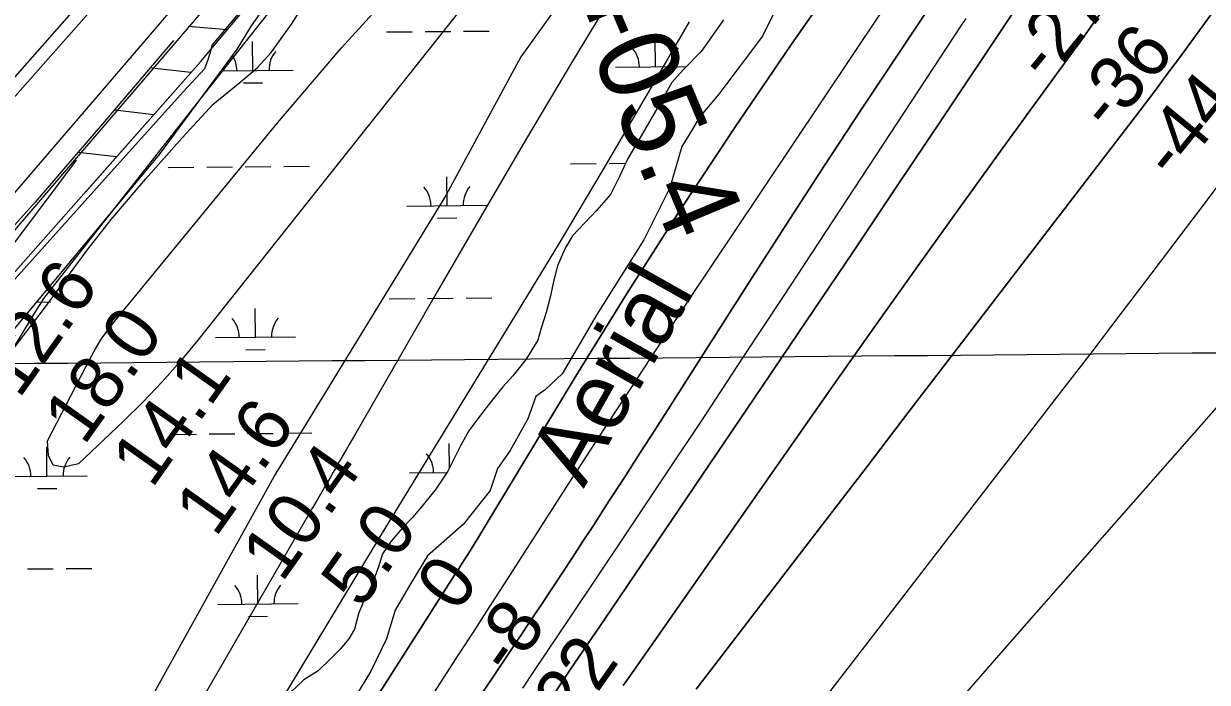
# Model space of a CAD drawing. Extents: x 3598634 to 3636690, y 517270 to 542944.
# Drawn here: x 3604186 to 3605662, y 528352 to 529174 of the extents above; entities that cross this region are included whole.
import ezdxf

# ---------------------------------------------------------------- set-up
doc = ezdxf.new("R2010")
doc.units = 0
for name, color, linetype in [('V-FLOD-BASE', 7, 'Continuous'), ('V-GRID-MAJR', 7, 'Continuous'), ('V-LEVE-TOET', 7, 'Continuous'), ('V-RIVR-EDGE', 7, 'Continuous'), ('V-RIVR-IDEN', 7, 'Continuous'), ('V-RIVR-RANG', 7, 'Continuous'), ('V-ROAD-CNTR', 7, 'Continuous'), ('V-RRAP-FSHR', 7, 'Continuous'), ('V-SITE-VEGE', 7, 'Continuous'), ('V-SURV-IDEN', 7, 'Continuous'), ('V-SURV-LINE', 7, 'Continuous'), ('V-TOPO-DPTH', 7, 'Continuous'), ('V-TOPO-MAJR', 7, 'Continuous'), ('V-TOPO-MINR', 7, 'Continuous'), ('V-TOPO-WATR', 7, 'Continuous'), ('V-WETL-SWMP', 7, 'Continuous')]:
    doc.layers.add(name, color=color, linetype=linetype)

msp = doc.modelspace()

# ---------------------------------------------------------------- linework, layer by layer
at = {"layer": 'V-FLOD-BASE'}
msp.add_lwpolyline([(3604373.2, 529152.8), (3604289.3, 529054.6), (3604200.6, 528951.2), (3604076.2, 528813.1), (3603925.5, 528633), (3603780.1, 528463.8), (3603729.2, 528402.9)], dxfattribs=at)
at = {"layer": 'V-GRID-MAJR'}
msp.add_spline([(3602797.9, 528737.7), (3608075.8, 528784.9), (3613353.8, 528832.9), (3618631.7, 528881.6), (3623909.7, 528931.1), (3629187.6, 528981.4), (3634465.5, 529032.5), (3634465.6, 529032.5)], degree=3, dxfattribs=at)
at = {"layer": 'V-LEVE-TOET'}
for points in [[(3605056.3, 530112.1), (3604790.8, 529796.4), (3604573.6, 529540.7), (3604353.6, 529284.8), (3604111.5, 529011.5), (3603916.4, 528772.2)], [(3605050.3, 529879.7), (3604869.8, 529677.4), (3604720.6, 529504.1), (3604655.2, 529427.9), (3604632.9, 529402.5), (3604606.9, 529368.5), (3604570.5, 529321.8), (3604548.7, 529296.4), (3604525.3, 529269.3), (3604483.9, 529222.5), (3604421.3, 529147.5), (3604419.3, 529139.5), (3604415.7, 529128.7), (3604411.5, 529117.3), (3604385.3, 529089), (3604295.3, 528989), (3604145.9, 528823), (3604017, 528671.5)]]:
    msp.add_lwpolyline(points, dxfattribs=at)
at = {"layer": 'V-RIVR-EDGE'}
msp.add_lwpolyline([(3605143.9, 529232), (3605107.6, 529158), (3605052.8, 529085.8), (3605028.9, 529057.1), (3605019, 529039.9), (3605006.7, 529020.4), (3604991.9, 528968.9), (3604959.3, 528904.1), (3604900.8, 528811.1), (3604857.7, 528737), (3604836.9, 528717.5), (3604824.6, 528708.9), (3604814.7, 528680.8), (3604792.6, 528641.6), (3604777.2, 528619), (3604767.9, 528591.4), (3604734.1, 528549.2), (3604689.9, 528510.1), (3604668.4, 528475.3), (3604649.3, 528442.2), (3604638.8, 528406.7), (3604619.1, 528366.3), (3604599.4, 528333.9)], dxfattribs=at)
at = {"layer": 'V-ROAD-CNTR'}
msp.add_lwpolyline([(3605050.3, 530130.1), (3604771, 529801.9), (3604661.3, 529672.6), (3604570.1, 529565.2), (3604473.3, 529450.7), (3604385.1, 529346.4), (3604329.2, 529282.9), (3604137.8, 529065.5), (3604133.8, 529061), (3603910.1, 528798.8), (3603670.9, 528524.4), (3603437, 528243.4)], dxfattribs=at)
at = {"layer": 'V-RRAP-FSHR'}
for p, q in [((3604440, 529166.1), (3604391.4, 529170.3)), ((3604394.7, 529112.7), (3604346.2, 529118.2)), ((3604348.4, 529060.2), (3604299.9, 529065.7)), ((3604302.1, 529007.7), (3604253.6, 529013.2))]:
    msp.add_line(p, q, dxfattribs=at)
for points in [[(3603091.9, 527329.5), (3603199.9, 527468.8), (3603247.5, 527548.8), (3603278.3, 527622.7), (3603286.7, 527683.9), (3603300.5, 527779.2), (3603315.4, 527834.6), (3603329.5, 527870), (3603360.8, 527909.2), (3603408.7, 527958.4), (3603635.1, 528229.7), (3603874.5, 528509.5), (3604166.6, 528854.3), (3604406.6, 529126.1), (3604875.1, 529685.7), (3605090, 529929.6)], [(3604263.2, 528963.7), (3604406.6, 529126.1), (3604800.2, 529596.2)]]:
    msp.add_lwpolyline(points, dxfattribs=at)
at = {"layer": 'V-SITE-VEGE'}
for p, q in [((3604886.8, 529244.8), (3604806.2, 529132.3)), ((3604520, 529173), (3604544, 529210.9)), ((3604494.6, 529137.6), (3604520, 529173)), ((3604477.2, 529118.5), (3604494.6, 529137.6)), ((3604806.2, 529132.3), (3604712.4, 528959.5)), ((3604455.6, 529100.5), (3604477.2, 529118.5)), ((3604422.3, 529073.2), (3604455.6, 529100.5)), ((3604383.9, 529031.3), (3604422.3, 529073.2)), ((3604338.1, 528979.7), (3604383.9, 529031.3)), ((3604295.3, 528929.3), (3604338.1, 528979.7)), ((3604712.4, 528959.5), (3604500.4, 528612.5)), ((3604265.3, 528891.3), (3604295.3, 528929.3)), ((3604211.1, 528817.3), (3604265.3, 528891.3)), ((3604171.3, 528765.8), (3604211.1, 528817.3)), ((3604500.4, 528612.5), (3604322.2, 528291.7))]:
    msp.add_line(p, q, dxfattribs=at)
at = {"layer": 'V-SURV-LINE'}
for points in [[(3603326, 527973.1), (3604734.6, 529615.8)], [(3604757.4, 529596.2), (3603348.8, 527953.6)]]:
    msp.add_lwpolyline(points, dxfattribs=at)
at = {"layer": 'V-TOPO-DPTH'}
for points in [[(3604845.8, 528335.7), (3604867.3, 528367.4), (3604888.8, 528399.2), (3604910.3, 528430.9), (3605107.1, 528721.4), (3605163.3, 528804.6), (3605219.5, 528887.9), (3605275.5, 528971.4), (3605331.4, 529054.9), (3605410.1, 529172.8), (3605426.6, 529197.4), (3605443, 529221.9), (3605459.6, 529246.4), (3605476.1, 529270.9), (3605537, 529360.8), (3605584.1, 529430.1), (3605631.4, 529499.3), (3605678.9, 529568.4), (3605726.6, 529637.3), (3606120.2, 530204.3)], [(3606120.2, 530204.3), (3605726.6, 529637.3), (3605678.9, 529568.4), (3605631.4, 529499.3), (3605584.1, 529430.1), (3605537, 529360.8), (3605476.1, 529270.9), (3605459.6, 529246.4), (3605443, 529221.9), (3605426.6, 529197.4), (3605410.1, 529172.8), (3605331.4, 529054.9), (3605275.5, 528971.4), (3605219.5, 528887.9), (3605163.3, 528804.6), (3605107.1, 528721.4), (3604910.3, 528430.9), (3604888.8, 528399.2), (3604867.3, 528367.4), (3604845.8, 528335.7)], [(3605024.7, 528344), (3605083.8, 528420.9), (3605135.1, 528487.9), (3605186.4, 528554.8), (3605237.8, 528621.7), (3605289.1, 528688.7), (3605573.7, 529059.5), (3605586.9, 529076.9), (3605600.1, 529094.3), (3605613, 529111.8), (3605626, 529129.4), (3605745.9, 529294.1), (3605818.7, 529394.1), (3605891.6, 529494), (3605964.5, 529594), (3606037.5, 529693.9), (3606273.1, 530016.3)], [(3606273.1, 530016.3), (3606037.5, 529693.9), (3605964.5, 529594), (3605891.6, 529494), (3605818.7, 529394.1), (3605745.9, 529294.1), (3605626, 529129.4), (3605613, 529111.8), (3605600.1, 529094.3), (3605586.9, 529076.9), (3605573.7, 529059.5), (3605289.1, 528688.7), (3605237.8, 528621.7), (3605186.4, 528554.8), (3605135.1, 528487.9), (3605083.8, 528420.9), (3605024.7, 528344)], [(3604933.7, 528348.5), (3604946.8, 528367.3), (3605196.3, 528723.6), (3605248.4, 528797.4), (3605300.7, 528871.1), (3605353.4, 528944.5), (3605406.3, 529017.7), (3605494, 529138.2), (3605503.3, 529151), (3605512.5, 529163.9), (3605521.7, 529176.8), (3605530.9, 529189.7), (3605600.5, 529288.5), (3605644.1, 529351.1), (3605687.2, 529413.9), (3605729.7, 529477.3), (3605771.8, 529540.9), (3605859.2, 529674.6), (3605898.9, 529735), (3605938.7, 529795.4), (3605978.6, 529855.6), (3606018.7, 529915.8)], [(3606018.7, 529915.8), (3605978.6, 529855.6), (3605938.7, 529795.4), (3605898.9, 529735), (3605859.2, 529674.6), (3605771.8, 529540.9), (3605729.7, 529477.3), (3605687.2, 529413.9), (3605644.1, 529351.1), (3605600.5, 529288.5), (3605530.9, 529189.7), (3605521.7, 529176.8), (3605512.5, 529163.9), (3605503.3, 529151), (3605494, 529138.2), (3605406.3, 529017.7), (3605353.4, 528944.5), (3605300.7, 528871.1), (3605248.4, 528797.4), (3605196.3, 528723.6), (3604946.8, 528367.3), (3604933.7, 528348.5)], [(3605249.9, 529300.6), (3605142.8, 529146.8), (3605072.9, 529044.3), (3605004.3, 528940.9), (3604937.8, 528836.2), (3604872.5, 528730.7), (3604751.9, 528531.2), (3604748, 528524.8), (3604744, 528518.3), (3604740, 528511.9), (3604735.9, 528505.6), (3604733.7, 528502.1), (3604730.8, 528497.5), (3604727.8, 528492.8), (3604724.8, 528488.2), (3604721.8, 528483.6), (3604718.8, 528479), (3604715.9, 528474.4), (3604712.9, 528469.7), (3604709.9, 528465.1), (3604239.5, 527726.4)], [(3604239.5, 527726.4), (3604709.9, 528465.1), (3604712.9, 528469.7), (3604715.9, 528474.4), (3604718.8, 528479), (3604721.8, 528483.6), (3604724.8, 528488.2), (3604727.8, 528492.8), (3604730.8, 528497.5), (3604733.7, 528502.1), (3604735.9, 528505.6), (3604740, 528511.9), (3604744, 528518.3), (3604748, 528524.8), (3604751.9, 528531.2), (3604872.5, 528730.7), (3604937.8, 528836.2), (3605004.3, 528940.9), (3605072.9, 529044.3), (3605142.8, 529146.8), (3605249.9, 529300.6)], [(3605345.1, 529238.9), (3605278.1, 529138.3), (3605230.8, 529067), (3605183.8, 528995.4), (3605137.2, 528923.6), (3605090.9, 528851.5), (3604973.8, 528668.1), (3604954.6, 528638.1), (3604935.3, 528608), (3604915.9, 528578.1), (3604896.5, 528548.1), (3604883.1, 528527.4), (3604870.4, 528507.9), (3604857.6, 528488.4), (3604844.7, 528468.9), (3604831.8, 528449.5), (3604813.7, 528422.3), (3604809.8, 528416.5), (3604806, 528410.7), (3604802.1, 528404.9), (3604798.3, 528399.2), (3604199.6, 527503.6)], [(3604199.6, 527503.6), (3604798.3, 528399.2), (3604802.1, 528404.9), (3604806, 528410.7), (3604809.8, 528416.5), (3604813.7, 528422.3), (3604831.8, 528449.5), (3604844.7, 528468.9), (3604857.6, 528488.4), (3604870.4, 528507.9), (3604883.1, 528527.4), (3604896.5, 528548.1), (3604915.9, 528578.1), (3604935.3, 528608), (3604954.6, 528638.1), (3604973.8, 528668.1), (3605090.9, 528851.5), (3605137.2, 528923.6), (3605183.8, 528995.4), (3605230.8, 529067), (3605278.1, 529138.3), (3605345.1, 529238.9)], [(3604926.2, 529219.3), (3604869.4, 529124.9), (3604813, 529030.3), (3604757.4, 528935.3), (3604702.1, 528840), (3604600.2, 528663), (3604596.2, 528656.1), (3604592.2, 528649.1), (3604588.2, 528642.2), (3604584.2, 528635.2), (3604580.2, 528628.3), (3604576.2, 528621.3), (3604572.2, 528614.4), (3604568.2, 528607.5), (3604566.3, 528604.2), (3604561.3, 528595.6), (3604556.3, 528587), (3604551.4, 528578.4), (3604546.4, 528569.8), (3604348.9, 528227.9)]]:
    msp.add_lwpolyline(points, dxfattribs=at)
at = {"layer": 'V-TOPO-MAJR'}
msp.add_lwpolyline([(3606410.5, 529960.7), (3606338.7, 529867.2), (3606297.8, 529813.6), (3606257.1, 529759.9), (3606216.7, 529705.9), (3606176.6, 529651.7), (3605749.4, 529071.5), (3605726.4, 529040.4), (3605703.4, 529009.4), (3605680.2, 528978.4), (3605657, 528947.5), (3605629.1, 528910.6), (3605591.8, 528861.3), (3605554.4, 528812.1), (3605516.8, 528763), (3605479.1, 528714), (3605128, 528259)], dxfattribs=at)
at = {"layer": 'V-TOPO-MINR'}
for points in [[(3605455.6, 530362.7), (3604918.8, 529698.1), (3604908.1, 529684.9), (3604897.3, 529671.8), (3604886.3, 529658.7), (3604875.4, 529645.7), (3604732.8, 529478.9), (3604651, 529382), (3604570.1, 529284.5), (3604490.4, 529186), (3604411.5, 529086.8), (3604219.9, 528842.7), (3604215.4, 528836.8), (3604211.1, 528830.8), (3604207, 528824.7), (3604203, 528818.4), (3604074.2, 528606.6), (3604034.4, 528543.7)], [(3606051.8, 530242.9), (3605366.7, 529350.5), (3605361.7, 529343.9), (3605356.6, 529337.2), (3605351.7, 529330.6), (3605346.7, 529323.9), (3605341.9, 529317.2), (3605337.1, 529310.4), (3605332.3, 529303.6), (3605327.7, 529296.7), (3605071.1, 528912.9), (3605019.1, 528834.7), (3604967.3, 528756.3), (3604916, 528677.7), (3604864.9, 528598.9), (3604796.4, 528492.6), (3604779.8, 528466.8), (3604763.1, 528441), (3604746.5, 528415.1), (3604729.8, 528389.3), (3604653.7, 528271.2)], [(3606120.2, 530204.3), (3605726.6, 529637.3), (3605678.9, 529568.4), (3605631.4, 529499.3), (3605584.1, 529430.1), (3605537, 529360.8), (3605476.1, 529270.9), (3605459.6, 529246.4), (3605443, 529221.9), (3605426.6, 529197.4), (3605410.1, 529172.8), (3605331.4, 529054.9), (3605275.5, 528971.4), (3605219.5, 528887.9), (3605163.3, 528804.6), (3605107.1, 528721.4), (3604910.3, 528430.9), (3604888.8, 528399.2), (3604867.3, 528367.4), (3604845.8, 528335.7)], [(3606273.1, 530016.3), (3606037.5, 529693.9), (3605964.5, 529594), (3605891.6, 529494), (3605818.7, 529394.1), (3605745.9, 529294.1), (3605626, 529129.4), (3605613, 529111.8), (3605600.1, 529094.3), (3605586.9, 529076.9), (3605573.7, 529059.5), (3605289.1, 528688.7), (3605237.8, 528621.7), (3605186.4, 528554.8), (3605135.1, 528487.9), (3605083.8, 528420.9), (3605024.7, 528344)], [(3606018.7, 529915.8), (3605978.6, 529855.6), (3605938.7, 529795.4), (3605898.9, 529735), (3605859.2, 529674.6), (3605771.8, 529540.9), (3605729.7, 529477.3), (3605687.2, 529413.9), (3605644.1, 529351.1), (3605600.5, 529288.5), (3605530.9, 529189.7), (3605521.7, 529176.8), (3605512.5, 529163.9), (3605503.3, 529151), (3605494, 529138.2), (3605406.3, 529017.7), (3605353.4, 528944.5), (3605300.7, 528871.1), (3605248.4, 528797.4), (3605196.3, 528723.6), (3604946.8, 528367.3), (3604933.7, 528348.5)], [(3604955.5, 529474), (3604403.3, 528779), (3604381.4, 528752.6), (3604358.8, 528726.9), (3604335.1, 528702.1), (3604310.7, 528678), (3604254.4, 528624.8), (3604236.3, 528620.7), (3604223.1, 528623), (3604217.2, 528635.1), (3604216.1, 528653.6), (3604269.1, 528756.2), (3604275.8, 528768.3), (3604283, 528780.1), (3604291, 528791.4), (3604299.4, 528802.3), (3604503, 529050.6), (3604582.6, 529143.5), (3604664.8, 529234)], [(3605345.1, 529238.9), (3605278.1, 529138.3), (3605230.8, 529067), (3605183.8, 528995.4), (3605137.2, 528923.6), (3605090.9, 528851.5), (3604973.8, 528668.1), (3604954.6, 528638.1), (3604935.3, 528608), (3604915.9, 528578.1), (3604896.5, 528548.1), (3604883.1, 528527.4), (3604870.4, 528507.9), (3604857.6, 528488.4), (3604844.7, 528468.9), (3604831.8, 528449.5), (3604813.7, 528422.3), (3604809.8, 528416.5), (3604806, 528410.7), (3604802.1, 528404.9), (3604798.3, 528399.2), (3604199.6, 527503.6)], [(3604926.2, 529219.3), (3604869.4, 529124.9), (3604813, 529030.3), (3604757.4, 528935.3), (3604702.1, 528840), (3604600.2, 528663), (3604596.2, 528656.1), (3604592.2, 528649.1), (3604588.2, 528642.2), (3604584.2, 528635.2), (3604580.2, 528628.3), (3604576.2, 528621.3), (3604572.2, 528614.4), (3604568.2, 528607.5), (3604566.3, 528604.2), (3604561.3, 528595.6), (3604556.3, 528587), (3604551.4, 528578.4), (3604546.4, 528569.8), (3604348.9, 528227.9)], [(3605016, 529176.1), (3604962.5, 529083.6), (3604908.5, 528991.5), (3604853.7, 528899.8), (3604798.3, 528808.4), (3604632.1, 528536.7), (3604630, 528533.3), (3604628, 528529.9), (3604627.3, 528528.8), (3604626.6, 528527.6), (3604624.1, 528523.5), (3604622.1, 528520.2), (3604620.2, 528517), (3604618.2, 528513.8), (3604616.3, 528510.5), (3604288.5, 527967.2)], [(3605361, 529180.3), (3605354, 529169.6), (3605347, 529158.9), (3605132.4, 528832.2), (3605083.5, 528758.1), (3605034.5, 528684), (3604985.4, 528610), (3604936.1, 528536.2), (3604866.3, 528432), (3604851.8, 528410.3), (3604837.2, 528388.6), (3604822.7, 528367), (3604808.1, 528345.3)], [(3604251.8, 529003.4), (3604172.2, 528897.6), (3604162.6, 528884.7), (3604153.1, 528871.7), (3604143.8, 528858.6), (3604134.5, 528845.5), (3604125.2, 528832.3), (3604115.8, 528819.3), (3604106.2, 528806.4), (3604096.4, 528793.6), (3604088.3, 528783.1), (3604074, 528765.4), (3604059.4, 528748), (3604044.2, 528731.2), (3604028.6, 528714.7), (3604023.5, 528709.6)], [(3605821.3, 528863.5), (3605427.3, 528415.4), (3605387.4, 528369.8), (3605347.7, 528324)]]:
    msp.add_lwpolyline(points, dxfattribs=at)
at = {"layer": 'V-TOPO-WATR'}
msp.add_lwpolyline([(3605249.9, 529300.6), (3605142.8, 529146.8), (3605072.9, 529044.3), (3605004.3, 528940.9), (3604937.8, 528836.2), (3604872.5, 528730.7), (3604751.9, 528531.2), (3604748, 528524.8), (3604744, 528518.3), (3604740, 528511.9), (3604735.9, 528505.6), (3604733.7, 528502.1), (3604730.8, 528497.5), (3604727.8, 528492.8), (3604724.8, 528488.2), (3604721.8, 528483.6), (3604718.8, 528479), (3604715.9, 528474.4), (3604712.9, 528469.7), (3604709.9, 528465.1), (3604239.5, 527726.4)], dxfattribs=at)
at = {"layer": 'V-WETL-SWMP'}
for p, q in [((3604638.7, 529163.3), (3604670.7, 529163.6)), ((3604686.7, 529163.8), (3604718.7, 529164.1)), ((3604734.7, 529164.2), (3604766.7, 529164.5)), ((3604472.1, 529115.4), (3604471.7, 529151.3)), ((3604974, 529120), (3604973.6, 529156)), ((3604924, 529119.6), (3605012.5, 529120.4)), ((3604432.9, 529115), (3604522.1, 529115.8)), ((3604962.1, 529104.5), (3604986.1, 529104.7)), ((3604460.2, 529099.8), (3604484.2, 529100)), ((3604868.2, 528999), (3604900.2, 528999.3)), ((3604916.2, 528999.4), (3604936.8, 528999.6)), ((3604366.4, 528994.3), (3604398.4, 528994.6)), ((3604414.4, 528994.7), (3604446.4, 528995)), ((3604462.4, 528995.2), (3604494.4, 528995.5)), ((3604510.4, 528995.6), (3604542.4, 528995.9)), ((3604714.1, 528946.8), (3604713.8, 528982.8)), ((3604664.1, 528946.3), (3604764.1, 528947.2)), ((3604702.3, 528931.2), (3604726.3, 528931.5)), ((3604202.4, 528826.6), (3604219.9, 528826.7)), ((3604235.9, 528826.9), (3604267.9, 528827.2)), ((3604641.8, 528830.7), (3604673.8, 528831)), ((3604689.8, 528831.1), (3604721.8, 528831.4)), ((3604737.8, 528831.6), (3604769.8, 528831.9)), ((3604475.2, 528782.7), (3604474.8, 528818.7)), ((3604425.2, 528782.2), (3604525.2, 528783.2)), ((3604463.3, 528767.1), (3604487.3, 528767.4)), ((3604369.5, 528661.6), (3604401.5, 528661.9)), ((3604417.5, 528662.1), (3604449.5, 528662.4)), ((3604465.5, 528662.5), (3604497.5, 528662.8)), ((3604513.5, 528663), (3604545.5, 528663.3)), ((3604215.3, 528609.5), (3604215, 528645.5)), ((3604717.2, 528619.9), (3604716.9, 528650.1)), ((3604165.3, 528609), (3604265.3, 528609.9)), ((3604667.2, 528613.7), (3604714, 528614.1)), ((3604203.5, 528593.9), (3604227.5, 528594.1)), ((3604191, 528493.8), (3604223, 528494.1)), ((3604239, 528494.2), (3604271, 528494.5)), ((3604478.3, 528450), (3604477.9, 528486)), ((3604428.3, 528449.6), (3604528.3, 528450.5)), ((3604466.4, 528434.5), (3604490.4, 528434.7))]:
    msp.add_line(p, q, dxfattribs=at)
for points in [[(3603445.3, 527974.1), (3604040.8, 528632.6), (3604355.7, 529010.5), (3604453, 529142.2), (3604470.2, 529170.8), (3604510.3, 529228), (3604544.6, 529256.7), (3604573.3, 529268.1), (3604613.3, 529285.3), (3604750.8, 529468.5), (3605243.2, 530023.9)], [(3605059, 529178.6), (3605030.9, 529139), (3605008.5, 529116.3), (3604994.3, 529100.2), (3604981.4, 529077.3), (3604954.6, 529030.9), (3604939.6, 529005.7), (3604929.6, 528984), (3604917.8, 528960.6), (3604900.4, 528940.9), (3604870.4, 528909.1), (3604861.2, 528893.6), (3604851.7, 528871.9)], [(3604851.7, 528871.9), (3604847.2, 528853.8), (3604842.7, 528832.8), (3604837.7, 528813.5), (3604831.5, 528794.2), (3604827.4, 528778.9), (3604812.9, 528755.4), (3604796.1, 528734.6), (3604783.5, 528720.7), (3604768.8, 528702.3), (3604755.8, 528685.6), (3604741.2, 528666), (3604731, 528647.1), (3604715.1, 528615.7), (3604700, 528593.3), (3604684.2, 528573.7), (3604671.1, 528558.1), (3604659.1, 528545.4), (3604644.4, 528528.6), (3604633.6, 528512.5), (3604628.5, 528496.6), (3604620.1, 528472.7), (3604610, 528453.3), (3604603.7, 528437.9), (3604598.6, 528418.6), (3604591.7, 528406.6), (3604580.8, 528393.9), (3604568.2, 528381.1), (3604553.4, 528366.6), (3604535.7, 528355.4), (3604519.3, 528340.3)]]:
    msp.add_lwpolyline(points, dxfattribs=at)
for centre, start, end in [((3604416.8, 529115.3), 359.7615, 31.6502), ((3604527.3, 529116.3), 139.7615, 181.3052), ((3604918.7, 529120), 359.7615, 41.3052), ((3605029.2, 529121), 139.7615, 181.3052), ((3604658.9, 528946.7), 359.7615, 41.3052), ((3604769.4, 528947.8), 139.7615, 181.3052), ((3604530.4, 528783.7), 139.7615, 181.3052), ((3604419.9, 528782.7), 359.7615, 41.3052), ((3604160.1, 528609.4), 359.7615, 41.3052), ((3604270.6, 528610.4), 139.7615, 181.3052), ((3604662, 528614.1), 359.7615, 41.3052), ((3604423, 528450), 359.7615, 41.3052), ((3604533.5, 528451), 139.7615, 181.3052)]:
    msp.add_arc(centre, 35.2, start, end, dxfattribs=at)

# ---------------------------------------------------------------- texts
at = {"layer": 'V-RIVR-IDEN'}
msp.add_text('Aerial', height=83, rotation=60.614, dxfattribs=at).set_placement((3604884.4, 528593.4))
at = {"layer": 'V-RIVR-RANG'}
for s, rotation, p in [('-27', 50.7334, (3605462, 529099)), ('-36', 50.7334, (3605540.6, 529037.1)), ('-44', 50.7334, (3605620.3, 528976.7)), ('12.6', 54.6283, (3604180.4, 528704.8)), ('18.0', 54.6283, (3604261.4, 528646.3)), ('14.1', 54.6283, (3604346.2, 528592.9)), ('14.6', 54.6283, (3604425.4, 528531.8)), ('10.4', 54.6283, (3604508.2, 528475.6)), ('5.0', 54.6283, (3604607.4, 528442.6)), ('0', 54.9118, (3604726.7, 528437.7)), ('-8', 54.9118, (3604793.4, 528358.7)), ('-22', 54.9118, (3604855.4, 528272.9))]:
    msp.add_text(s, height=67, rotation=rotation, dxfattribs=at).set_placement(p)
at = {"layer": 'V-SURV-IDEN'}
msp.add_text('5783+05.4', height=100, rotation=292.6583, dxfattribs=at).set_placement((3604748.7, 529485.1))

doc.saveas('drawing.dxf')
